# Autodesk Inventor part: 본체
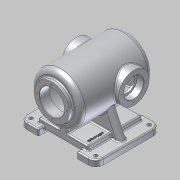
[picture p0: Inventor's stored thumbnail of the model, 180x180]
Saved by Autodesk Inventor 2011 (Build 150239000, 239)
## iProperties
Created: 2013-06
Part Number: 본체
Document SubType Name: Modeling
Designer: SeoGD™[esajin.kr]
Density: 1 g/cm^3
Author: SeoGD™[esajin.kr]
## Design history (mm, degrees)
sketch "스케치1"
  geometry: L1 (-100, 85)-(-50, 85); L2 (-50, 85)-(-50, -85); L3 (-50, -85)-(-100, -85); L4 (-100, -85)-(-100, 85); L5 (50, 85)-(100, 85); L6 (100, 85)-(100, -85); L7 (100, -85)-(50, -85); L8 (50, -85)-(50, 85); 3 further points
  constraints: 16 end point, 4 parallel, 2 equal length, 2 horizontal, 2 horizontal alignment, 2 midpoint, 2 perpendicular
  dimensions: "d0" = 100 distance between parallel lines of L8 L2; "d1" = 170 distance of L3.end L1.start; "d3" = 200 distance between parallel lines of L6 L4; "d4" = 50 distance from line of point (0, 0) L2 (= 0.5 x d0)
extrude "돌출1" new body sketch "스케치1" distance "d5" = 16; taper "d6" = 0 deg
node "작업 평면1"
sketch "스케치2"
  geometry: L1 (-65, 70)-(65, 70); L2 (65, 70)-(65, -70); L3 (65, -70)-(-65, -70); L4 (-65, -70)-(-65, 70); 3 further points
  constraints: 8 end point, 2 midpoint, 2 parallel, 1 horizontal, 1 horizontal alignment, 1 perpendicular, 1 vertical alignment
  dimensions: "d8" = 130 distance of L2.end L3.end; "d9" = 140 distance of L1.end L2.end
extrude "돌출2" join sketch "스케치2" distance "d10" = 20; taper "d11" = 0 deg
sketch "스케치3"
  geometry: L1 (-100, 110)-(100, 110); L2 (85, 0)-(-85, 0) reference; L3 (100, 110)-(100, 175); L4 (100, 175)-(-90, 175); L5 (-90, 175)-(-90, 156); L6 (-90, 156)-(-100, 156); L7 (-100, 156)-(-100, 110); L8 (90, 110)-(90, 165); L9 (90, 165)-(-75, 165); L10 (-75, 165)-(-75, 110); L11 (-100, 142.5)-(-75, 142.5); 3 further points
  constraints: 20 end point, 5 perpendicular, 4 parallel, 4 point on line, 2 midpoint, 1 horizontal, 1 vertical alignment
  dimensions: "d12" = 110 distance from line of L2 L1.end; "d13" = 200 distance of L1.start L1.end; "d14" = 130 diameter of L4 L1; "d15" = 92 diameter of L6 L1; "d16" = 10 distance of L5.end L6.end; "d42" = 110 diameter of L9 L1; "d43" = 10 distance between parallel lines of L3 L8; "d44" = 25 distance between parallel lines of L10 L7; "d45" = 65 diameter of L11 L1
revolve "회전1" sketch "스케치3" stored, may be unused: angle "d17" = 90 deg
sketch "스케치4"
  geometry: L1 (-50, 70)-(50, 70) reference; L2 (50, -70)-(-50, -70) reference; L3 (-10, 70)-(-10, -70); L4 (10, -70)-(10, 70); 1 further point
  constraints: 4 end point, 4 point on line, 2 perpendicular
  dimensions: "d18" = 20 distance between parallel lines of L4 L3; "d19" = 10 distance from line of point (0, 0) L3
extrude "돌출3" join sketch "스케치4" stored distance "d20" = 10; taper "d21" = 0 deg
node "작업 평면2"
sketch "스케치5"
  geometry: L1 (-50, -8)-(0, -8) reference; L2 (100, -8)-(150, -8) reference; L3 (-40, -8)-(-8.943, -74.601); L4 (140, -8)-(108.943, -74.601); L5 (-50, 8)-(-50, -8) reference; L6 (150, 8)-(150, -8) reference; A1 r 65 centre (50, -102) between (-8.943, -74.601) and (108.943, -74.601) reference; 1 further point
  constraints: 4 end point, 2 point on circle, 2 point on line, 1 equal length
  dimensions: "d23" = 10 distance from line of L3.start L5; "d24" = 10 distance from line of L4.start L6; "d25" = 25 deg angle of L3 L5
feature "리브1" sketch "스케치5" dims "d26" = 1, "d27" = 20, "d28" = 0
node "작업 평면3"
sketch "스케치6"
  geometry: L1 (100, 156)-(100, 64) reference; C1 r 40 at (-40, 110); 2 further points
  constraints: 1 centre point, 1 horizontal alignment, 1 midpoint
  dimensions: "d37" = 80 diameter of C1; "d38" = 140 distance from line of C1.centre L1
extrude "돌출4" join sketch "스케치6" stored distance "d39" = 10; taper "d40" = 0 deg
hole "구멍1" diameter "d48" = 42; stored, may be unused: countersink angle "d52" = 90 deg, drill point angle "d54" = 118 deg; dims "d46" = 10, "d47" = 10, "d49" = 6, "d50" = 52, "d51" = 18, "d53" = 8
sketch "스케치7"
  geometry: C1 r 40 at (0, 0) reference; 2 further points
  constraints: 1 horizontal alignment
  dimensions: "d55" = 32.5 distance of point (32.5, 0) C1.centre
hole "구멍2" sketch "스케치7" at (32.5, 0) diameter "d56" = 3.242; stored, may be unused: countersink angle "d60" = 90 deg, drill point angle "d62" = 118 deg; dims "d57" = 10, "d58" = 52, "d59" = 18, "d61" = 13
sketch "스케치8"
  geometry: C1 r 46 at (0, 0) reference; 2 further points
  constraints: 1 vertical alignment
  dimensions: "d66" = 39 distance of C1.centre point (0, 39)
hole "구멍3" sketch "스케치8" at (0, 39) diameter "d67" = 3.242; stored, may be unused: countersink angle "d71" = 90 deg, drill point angle "d73" = 118 deg; dims "d68" = 10, "d69" = 52, "d70" = 18, "d72" = 13
fillet "모깎기7" dims "d77" = 20, "d78" = 13, "d79" = 3, "d80" = 10
fillet "모깎기8" dims "d81" = 3
fillet "모깎기9" dims "d82" = 3
fillet "모깎기10" dims "d83" = 3, "d84" = 0.3
chamfer "모따기1" distance "d85" = 1; stored, may be unused: second distance "d86" = 2, angle "d87" = 45 deg
node "작업 평면4"
sketch "스케치10"
  geometry: 5 further points
  constraints: 2 horizontal alignment, 2 vertical alignment
  dimensions: "d90" = 170 distance of point (85, 70) point (-85, 70); "d91" = 140 distance of point (-85, 70) point (-85, -70); "d92" = 70 vertical distance of point (0, 0) point (-85, -70) (= 0.5 x d91); "d93" = 85 horizontal distance of point (0, 0) point (-85, 70) (= 0.5 x d90)
hole "구멍4" sketch "스케치10" at (-85, 70), (85, 70), (85, -70), (-85, -70) diameter "d94" = 10; stored, may be unused: countersink angle "d98" = 90 deg, drill point angle "d100" = 118 deg; dims "d95" = 6, "d96" = 4, "d97" = 2, "d99" = 8
sketch "스케치11"
  geometry: L1 (13, -70)-(62, -70) reference; L2 (65, -67)-(65, -13) reference; 2 further points
  constraints: 1 other
  dimensions: "d101" = 30 distance from line of point (55, -40) L1; "d102" = 10 distance from line of point (55, -40) L2
feature "엠보싱2" sketch "스케치11" dims "d0" = 100, "d1" = 170, "d3" = 200, "d4" = 50 (= 0.5 x d0), "d103" = 1, "d104" = 0
node "솔리드1"
mirror "대칭1"
pattern_circular "원형 패턴1" dims angle "d64" = 360 deg
mirror "대칭3"
pattern_circular "원형 패턴2" dims angle "d75" = 360 deg
other parameters: "d7" = 8, "d36" = -75
